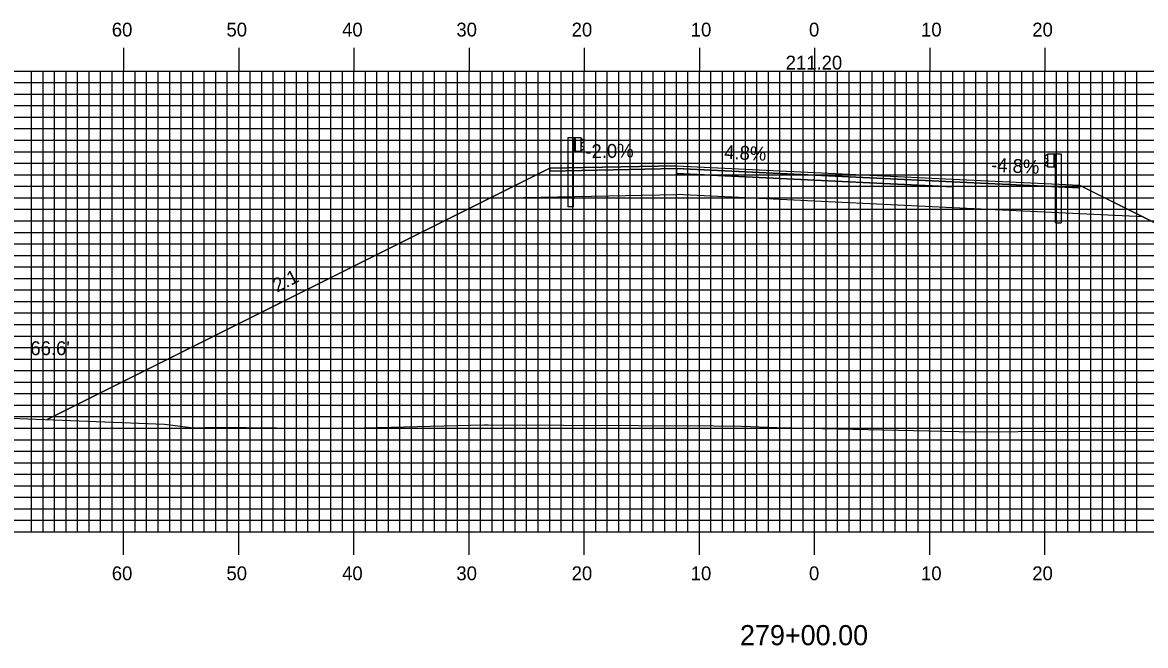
# Model space of a CAD drawing. Extents: x 1810587 to 1810930, y 442591 to 442811.
# Drawn here: x 1810683.6 to 1810781.1, y 442658.8 to 442712.9 of the extents above; entities that cross this region are included whole.
import ezdxf

# ---------------------------------------------------------------- set-up
doc = ezdxf.new("R2010")
doc.units = 0
for name, color, linetype in [('ANNOTATION', 7, 'Continuous'), ('D_Guardrail_Beam_Lt', 7, 'Continuous'), ('D_Guardrail_Beam_Rt', 7, 'Continuous'), ('D_Roadway_Centerline', 7, 'Continuous'), ('D_Roadway_Centerline_Text', 7, 'Continuous'), ('D_Roadway_Edge_Shoulder', 7, 'Continuous'), ('D_Roadway_Edge_TW', 7, 'Continuous'), ('D_Roadway_Pavement', 7, 'Continuous'), ('D_Roadway_SlopeLines', 7, 'Continuous'), ('D_Roadway_SubGrade', 7, 'Continuous'), ('D_Text_Standard', 7, 'Continuous'), ('H_V ANNOTATION', 7, 'Continuous'), ('MAJOR', 7, 'Continuous'), ('MINOR', 7, 'Continuous'), ('S_Roadway_Centerline', 7, 'Continuous')]:
    doc.layers.add(name, color=color, linetype=linetype)

msp = doc.modelspace()

# ---------------------------------------------------------------- linework, layer by layer
at = {"layer": 'D_Guardrail_Beam_Lt'}
for p, q in [((1810730.947, 442702.87), (1810730.947, 442696.87)), ((1810731.418, 442702.87), (1810730.947, 442702.87)), ((1810732.106, 442702.87), (1810731.418, 442702.87)), ((1810731.418, 442702.87), (1810731.418, 442701.703)), ((1810731.481, 442702.87), (1810731.481, 442701.703)), ((1810731.585, 442702.87), (1810731.585, 442701.703)), ((1810732.106, 442701.703), (1810732.106, 442702.87)), ((1810732.106, 442702.786), (1810732.18, 442702.772)), ((1810732.11, 442702.321), (1810732.11, 442702.251)), ((1810732.339, 442702.522), (1810732.144, 442702.386)), ((1810732.144, 442702.187), (1810732.339, 442702.051)), ((1810732.196, 442702.765), (1810732.339, 442702.665)), ((1810732.339, 442701.907), (1810732.196, 442701.807)), ((1810731.418, 442701.703), (1810732.106, 442701.703)), ((1810731.439, 442696.87), (1810731.439, 442701.703)), ((1810732.18, 442701.801), (1810732.106, 442701.786)), ((1810731.439, 442696.87), (1810730.947, 442696.87))]:
    msp.add_line(p, q, dxfattribs=at)
for centre, major_axis, start_param, end_param in [((1810732.189, 442702.321), (-0.0789, 0), 5.323254, 6.283185), ((1810732.189, 442702.251), (-0.0789, 0), 6.283185, 7.243116), ((1810732.172, 442702.731), (0.0417, 0), 0.959931, 1.376053), ((1810732.289, 442702.593), (0.0877, 0), 5.323254, 7.243116), ((1810732.289, 442701.979), (0.0877, 0), 5.323254, 7.243116), ((1810732.172, 442701.841), (0.0417, 0), 4.907132, 5.323254)]:
    msp.add_ellipse(centre, major_axis=major_axis, ratio=0.995501, start_param=start_param, end_param=end_param, dxfattribs=at)
at = {"layer": 'D_Guardrail_Beam_Rt'}
for p, q in [((1810772.557, 442701.389), (1810772.414, 442701.289)), ((1810772.414, 442701.146), (1810772.609, 442701.01)), ((1810772.647, 442701.41), (1810772.573, 442701.396)), ((1810772.643, 442700.945), (1810772.643, 442700.875)), ((1810772.647, 442701.494), (1810773.335, 442701.494)), ((1810772.647, 442700.327), (1810772.647, 442701.494)), ((1810773.168, 442701.494), (1810773.168, 442700.327)), ((1810773.272, 442701.494), (1810773.272, 442700.327)), ((1810773.335, 442701.494), (1810773.806, 442701.494)), ((1810773.335, 442701.494), (1810773.335, 442700.327)), ((1810773.806, 442701.494), (1810773.806, 442695.494)), ((1810772.609, 442700.811), (1810772.414, 442700.675)), ((1810772.414, 442700.531), (1810772.557, 442700.431)), ((1810772.573, 442700.425), (1810772.647, 442700.41)), ((1810773.335, 442700.327), (1810772.647, 442700.327)), ((1810773.314, 442695.494), (1810773.314, 442700.327)), ((1810773.314, 442695.494), (1810773.806, 442695.494))]:
    msp.add_line(p, q, dxfattribs=at)
for centre, major_axis, start_param, end_param in [((1810772.464, 442701.217), (-0.0877, 0), 5.323254, 7.243116), ((1810772.581, 442701.355), (-0.0417, 0), 4.907132, 5.323254), ((1810772.564, 442700.945), (0.0789, 0), 0, 0.959931), ((1810772.464, 442700.603), (-0.0877, 0), 5.323254, 7.243116), ((1810772.581, 442700.465), (-0.0417, 0), 0.959931, 1.376053), ((1810772.564, 442700.875), (0.0789, 0), 5.323254, 6.283185)]:
    msp.add_ellipse(centre, major_axis=major_axis, ratio=0.995501, start_param=start_param, end_param=end_param, dxfattribs=at)
at = {"layer": 'D_Roadway_Centerline'}
msp.add_lwpolyline([(1810685.734, 442678.405), (1810724.168, 442697.622), (1810729.377, 442700.226), (1810732.377, 442700.286), (1810740.377, 442700.446), (1810752.377, 442699.87), (1810764.377, 442699.294), (1810772.377, 442698.91), (1810775.377, 442698.766), (1810780.908, 442696.001), (1810818.893, 442677.008)], dxfattribs=at)
at = {"layer": 'D_Roadway_Edge_Shoulder'}
for points in [[(1810740.377, 442700.446), (1810732.377, 442700.286), (1810732.377, 442700.286), (1810729.377, 442700.226), (1810729.377, 442699.976), (1810740.377, 442700.196)], [(1810764.377, 442699.294), (1810772.377, 442698.91), (1810772.377, 442698.91), (1810775.377, 442698.766), (1810775.377, 442698.516), (1810764.377, 442699.044)]]:
    msp.add_lwpolyline(points, close=True, dxfattribs=at)
at = {"layer": 'D_Roadway_Edge_TW'}
msp.add_lwpolyline([(1810740.377, 442700.196), (1810740.377, 442700.446), (1810752.377, 442699.87), (1810764.377, 442699.294), (1810764.377, 442699.044), (1810752.377, 442699.62)], close=True, dxfattribs=at)
at = {"layer": 'D_Roadway_Pavement'}
msp.add_lwpolyline([(1810740.377, 442699.78), (1810740.377, 442700.196), (1810752.377, 442699.62), (1810764.377, 442699.044), (1810764.377, 442698.628), (1810752.377, 442699.204)], close=True, dxfattribs=at)
for points in [[(1810740.377, 442700.196), (1810740.377, 442699.78)], [(1810764.377, 442699.044), (1810764.377, 442698.628)]]:
    msp.add_lwpolyline(points, dxfattribs=at)
at = {"layer": 'D_Roadway_SlopeLines'}
for points in [[(1810729.377, 442700.226), (1810685.734, 442678.405)], [(1810775.377, 442698.766), (1810818.893, 442677.008)]]:
    msp.add_lwpolyline(points, dxfattribs=at)
at = {"layer": 'D_Roadway_SubGrade'}
for points in [[(1810740.377, 442699.78), (1810740.377, 442700.196), (1810729.377, 442699.976), (1810729.377, 442700.226), (1810724.168, 442697.622), (1810740.377, 442697.946)], [(1810740.377, 442697.946), (1810740.377, 442700.196), (1810740.377, 442699.78), (1810752.377, 442699.204), (1810764.377, 442698.628), (1810764.377, 442699.044), (1810764.377, 442696.794), (1810752.377, 442697.37)], [(1810764.377, 442698.628), (1810764.377, 442699.044), (1810775.377, 442698.516), (1810775.377, 442698.766), (1810780.908, 442696.001), (1810764.377, 442696.794)]]:
    msp.add_lwpolyline(points, close=True, dxfattribs=at)
at = {"layer": 'MAJOR'}
for p, q in [((1810692.377, 442710.669), (1810692.377, 442708.665)), ((1810702.377, 442710.669), (1810702.377, 442708.665)), ((1810712.377, 442710.669), (1810712.377, 442708.665)), ((1810722.377, 442710.669), (1810722.377, 442708.665)), ((1810732.377, 442710.669), (1810732.377, 442708.665)), ((1810742.377, 442710.669), (1810742.377, 442708.665)), ((1810752.377, 442710.669), (1810752.377, 442708.665)), ((1810762.377, 442710.669), (1810762.377, 442708.665)), ((1810772.377, 442710.669), (1810772.377, 442708.665)), ((1810612.377, 442708.665), (1810892.377, 442708.665)), ((1810612.377, 442708.665), (1810892.377, 442708.665)), ((1810692.377, 442668.665), (1810692.377, 442708.665)), ((1810702.377, 442668.665), (1810702.377, 442708.665)), ((1810712.377, 442668.665), (1810712.377, 442708.665)), ((1810722.377, 442668.665), (1810722.377, 442708.665)), ((1810732.377, 442668.665), (1810732.377, 442708.665)), ((1810742.377, 442668.665), (1810742.377, 442708.665)), ((1810752.377, 442668.665), (1810752.377, 442708.665)), ((1810762.377, 442668.665), (1810762.377, 442708.665)), ((1810772.377, 442668.665), (1810772.377, 442708.665)), ((1810612.377, 442703.665), (1810892.377, 442703.665)), ((1810612.377, 442698.665), (1810892.377, 442698.665)), ((1810612.377, 442693.665), (1810892.377, 442693.665)), ((1810612.377, 442688.665), (1810892.377, 442688.665)), ((1810612.377, 442683.665), (1810892.377, 442683.665)), ((1810612.377, 442678.665), (1810892.377, 442678.665)), ((1810612.377, 442673.665), (1810892.377, 442673.665)), ((1810612.377, 442668.665), (1810892.377, 442668.665)), ((1810612.377, 442668.665), (1810892.377, 442668.665)), ((1810692.377, 442666.661), (1810692.377, 442668.665)), ((1810702.377, 442666.661), (1810702.377, 442668.665)), ((1810712.377, 442666.661), (1810712.377, 442668.665)), ((1810722.377, 442666.661), (1810722.377, 442668.665)), ((1810732.377, 442666.661), (1810732.377, 442668.665)), ((1810742.377, 442666.661), (1810742.377, 442668.665)), ((1810752.377, 442666.661), (1810752.377, 442668.665)), ((1810762.377, 442666.661), (1810762.377, 442668.665)), ((1810772.377, 442666.661), (1810772.377, 442668.665))]:
    msp.add_line(p, q, dxfattribs=at)
at = {"layer": 'MINOR'}
for p, q in [((1810684.377, 442668.665), (1810684.377, 442708.665)), ((1810685.377, 442668.665), (1810685.377, 442708.665)), ((1810686.377, 442668.665), (1810686.377, 442708.665)), ((1810687.377, 442668.665), (1810687.377, 442708.665)), ((1810688.377, 442668.665), (1810688.377, 442708.665)), ((1810689.377, 442668.665), (1810689.377, 442708.665)), ((1810690.377, 442668.665), (1810690.377, 442708.665)), ((1810691.377, 442668.665), (1810691.377, 442708.665)), ((1810693.377, 442668.665), (1810693.377, 442708.665)), ((1810694.377, 442668.665), (1810694.377, 442708.665)), ((1810695.377, 442668.665), (1810695.377, 442708.665)), ((1810696.377, 442668.665), (1810696.377, 442708.665)), ((1810697.377, 442668.665), (1810697.377, 442708.665)), ((1810698.377, 442668.665), (1810698.377, 442708.665)), ((1810699.377, 442668.665), (1810699.377, 442708.665)), ((1810700.377, 442668.665), (1810700.377, 442708.665)), ((1810701.377, 442668.665), (1810701.377, 442708.665)), ((1810703.377, 442668.665), (1810703.377, 442708.665)), ((1810704.377, 442668.665), (1810704.377, 442708.665)), ((1810705.377, 442668.665), (1810705.377, 442708.665)), ((1810706.377, 442668.665), (1810706.377, 442708.665)), ((1810707.377, 442668.665), (1810707.377, 442708.665)), ((1810708.377, 442668.665), (1810708.377, 442708.665)), ((1810709.377, 442668.665), (1810709.377, 442708.665)), ((1810710.377, 442668.665), (1810710.377, 442708.665)), ((1810711.377, 442668.665), (1810711.377, 442708.665)), ((1810713.377, 442668.665), (1810713.377, 442708.665)), ((1810714.377, 442668.665), (1810714.377, 442708.665)), ((1810715.377, 442668.665), (1810715.377, 442708.665)), ((1810716.377, 442668.665), (1810716.377, 442708.665)), ((1810717.377, 442668.665), (1810717.377, 442708.665)), ((1810718.377, 442668.665), (1810718.377, 442708.665)), ((1810719.377, 442668.665), (1810719.377, 442708.665)), ((1810720.377, 442668.665), (1810720.377, 442708.665)), ((1810721.377, 442668.665), (1810721.377, 442708.665)), ((1810723.377, 442668.665), (1810723.377, 442708.665)), ((1810724.377, 442668.665), (1810724.377, 442708.665)), ((1810725.377, 442668.665), (1810725.377, 442708.665)), ((1810726.377, 442668.665), (1810726.377, 442708.665)), ((1810727.377, 442668.665), (1810727.377, 442708.665)), ((1810728.377, 442668.665), (1810728.377, 442708.665)), ((1810729.377, 442668.665), (1810729.377, 442708.665)), ((1810730.377, 442668.665), (1810730.377, 442708.665)), ((1810731.377, 442668.665), (1810731.377, 442708.665)), ((1810733.377, 442668.665), (1810733.377, 442708.665)), ((1810734.377, 442668.665), (1810734.377, 442708.665)), ((1810735.377, 442668.665), (1810735.377, 442708.665)), ((1810736.377, 442668.665), (1810736.377, 442708.665)), ((1810737.377, 442668.665), (1810737.377, 442708.665)), ((1810738.377, 442668.665), (1810738.377, 442708.665)), ((1810739.377, 442668.665), (1810739.377, 442708.665)), ((1810740.377, 442668.665), (1810740.377, 442708.665)), ((1810741.377, 442668.665), (1810741.377, 442708.665)), ((1810743.377, 442668.665), (1810743.377, 442708.665)), ((1810744.377, 442668.665), (1810744.377, 442708.665)), ((1810745.377, 442668.665), (1810745.377, 442708.665)), ((1810746.377, 442668.665), (1810746.377, 442708.665)), ((1810747.377, 442668.665), (1810747.377, 442708.665)), ((1810748.377, 442668.665), (1810748.377, 442708.665)), ((1810749.377, 442668.665), (1810749.377, 442708.665)), ((1810750.377, 442668.665), (1810750.377, 442708.665)), ((1810751.377, 442668.665), (1810751.377, 442708.665)), ((1810753.377, 442668.665), (1810753.377, 442708.665)), ((1810754.377, 442668.665), (1810754.377, 442708.665)), ((1810755.377, 442668.665), (1810755.377, 442708.665)), ((1810756.377, 442668.665), (1810756.377, 442708.665)), ((1810757.377, 442668.665), (1810757.377, 442708.665)), ((1810758.377, 442668.665), (1810758.377, 442708.665)), ((1810759.377, 442668.665), (1810759.377, 442708.665)), ((1810760.377, 442668.665), (1810760.377, 442708.665)), ((1810761.377, 442668.665), (1810761.377, 442708.665)), ((1810763.377, 442668.665), (1810763.377, 442708.665)), ((1810764.377, 442668.665), (1810764.377, 442708.665)), ((1810765.377, 442668.665), (1810765.377, 442708.665)), ((1810766.377, 442668.665), (1810766.377, 442708.665)), ((1810767.377, 442668.665), (1810767.377, 442708.665)), ((1810768.377, 442668.665), (1810768.377, 442708.665)), ((1810769.377, 442668.665), (1810769.377, 442708.665)), ((1810770.377, 442668.665), (1810770.377, 442708.665)), ((1810771.377, 442668.665), (1810771.377, 442708.665)), ((1810773.377, 442668.665), (1810773.377, 442708.665)), ((1810774.377, 442668.665), (1810774.377, 442708.665)), ((1810775.377, 442668.665), (1810775.377, 442708.665)), ((1810776.377, 442668.665), (1810776.377, 442708.665)), ((1810777.377, 442668.665), (1810777.377, 442708.665)), ((1810778.377, 442668.665), (1810778.377, 442708.665)), ((1810779.377, 442668.665), (1810779.377, 442708.665)), ((1810780.377, 442668.665), (1810780.377, 442708.665)), ((1810612.377, 442707.665), (1810892.377, 442707.665)), ((1810612.377, 442706.665), (1810892.377, 442706.665)), ((1810612.377, 442705.665), (1810892.377, 442705.665)), ((1810612.377, 442704.665), (1810892.377, 442704.665)), ((1810612.377, 442702.665), (1810892.377, 442702.665)), ((1810612.377, 442701.665), (1810892.377, 442701.665)), ((1810612.377, 442700.665), (1810892.377, 442700.665)), ((1810612.377, 442699.665), (1810892.377, 442699.665)), ((1810612.377, 442697.665), (1810892.377, 442697.665)), ((1810612.377, 442696.665), (1810892.377, 442696.665)), ((1810612.377, 442695.665), (1810892.377, 442695.665)), ((1810612.377, 442694.665), (1810892.377, 442694.665)), ((1810612.377, 442692.665), (1810892.377, 442692.665)), ((1810612.377, 442691.665), (1810892.377, 442691.665)), ((1810612.377, 442690.665), (1810892.377, 442690.665)), ((1810612.377, 442689.665), (1810892.377, 442689.665)), ((1810612.377, 442687.665), (1810892.377, 442687.665)), ((1810612.377, 442686.665), (1810892.377, 442686.665)), ((1810612.377, 442685.665), (1810892.377, 442685.665)), ((1810612.377, 442684.665), (1810892.377, 442684.665)), ((1810612.377, 442682.665), (1810892.377, 442682.665)), ((1810612.377, 442681.665), (1810892.377, 442681.665)), ((1810612.377, 442680.665), (1810892.377, 442680.665)), ((1810612.377, 442679.665), (1810892.377, 442679.665)), ((1810612.377, 442677.665), (1810892.377, 442677.665)), ((1810612.377, 442676.665), (1810892.377, 442676.665)), ((1810612.377, 442675.665), (1810892.377, 442675.665)), ((1810612.377, 442674.665), (1810892.377, 442674.665)), ((1810612.377, 442672.665), (1810892.377, 442672.665)), ((1810612.377, 442671.665), (1810892.377, 442671.665)), ((1810612.377, 442670.665), (1810892.377, 442670.665)), ((1810612.377, 442669.665), (1810892.377, 442669.665))]:
    msp.add_line(p, q, dxfattribs=at)
at = {"layer": 'S_Roadway_Centerline'}
msp.add_lwpolyline([(1810612.377, 442680.56), (1810616.994, 442680.407), (1810617.324, 442680.393), (1810629.693, 442679.316), (1810644.567, 442679.499), (1810649.667, 442679.396), (1810659.943, 442679.186), (1810665.127, 442678.747), (1810671.183, 442678.589), (1810681.07, 442678.591), (1810695.918, 442678), (1810698.449, 442677.702), (1810700.449, 442677.756), (1810710.936, 442677.647), (1810723.662, 442677.959), (1810723.705, 442677.958), (1810723.739, 442677.958), (1810724.022, 442677.957), (1810743.64, 442677.873), (1810746.047, 442677.849), (1810749.124, 442677.72), (1810766.249, 442677.345), (1810773.84, 442677.406), (1810786.871, 442677.385)], dxfattribs=at)

# ---------------------------------------------------------------- texts
at = {"layer": 'ANNOTATION'}
for s, rotation, p in [('-2.0%', 1.14576, (1810732.483, 442701.089)), ('4.8%', 357.25191, (1810744.506, 442701.05)), ('-4.8%', 357.25191, (1810767.685, 442699.938)), ('2:1', 26.56505, (1810705.701, 442689.424))]:
    msp.add_text(s, height=1.2, rotation=rotation, dxfattribs=at).set_placement(p)
at = {"layer": 'D_Roadway_Centerline'}
for s, p in [('C', (1810752.371, 442699.87)), ('L', (1810752.377, 442699.863))]:
    msp.add_text(s, height=0.0146, dxfattribs=at).set_placement(p)
at = {"layer": 'D_Roadway_Centerline_Text'}
msp.add_text('211.20', height=1.2, dxfattribs=at).set_placement((1810749.872, 442708.799))
at = {"layer": 'D_Text_Standard'}
msp.add_text("66.6'", height=1.2, dxfattribs=at).set_placement((1810684.278, 442684.006))
at = {"layer": 'H_V ANNOTATION'}
for s, height, p in [('60', 1.2, (1810691.349, 442711.665)), ('50', 1.2, (1810701.306, 442711.665)), ('40', 1.2, (1810711.349, 442711.665)), ('30', 1.2, (1810721.274, 442711.665)), ('20', 1.2, (1810731.285, 442711.665)), ('10', 1.2, (1810741.627, 442711.665)), ('0', 1.2, (1810751.895, 442711.665)), ('10', 1.2, (1810761.627, 442711.665)), ('20', 1.2, (1810771.285, 442711.665)), ('60', 1.2, (1810691.349, 442664.465)), ('50', 1.2, (1810701.306, 442664.465)), ('40', 1.2, (1810711.349, 442664.465)), ('30', 1.2, (1810721.274, 442664.465)), ('20', 1.2, (1810731.285, 442664.465)), ('10', 1.2, (1810741.627, 442664.465)), ('0', 1.2, (1810751.895, 442664.465)), ('10', 1.2, (1810761.627, 442664.465)), ('20', 1.2, (1810771.285, 442664.465)), ('279+00.00', 1.75, (1810745.9, 442658.821))]:
    msp.add_text(s, height=height, dxfattribs=at).set_placement(p)

doc.saveas('drawing.dxf')
